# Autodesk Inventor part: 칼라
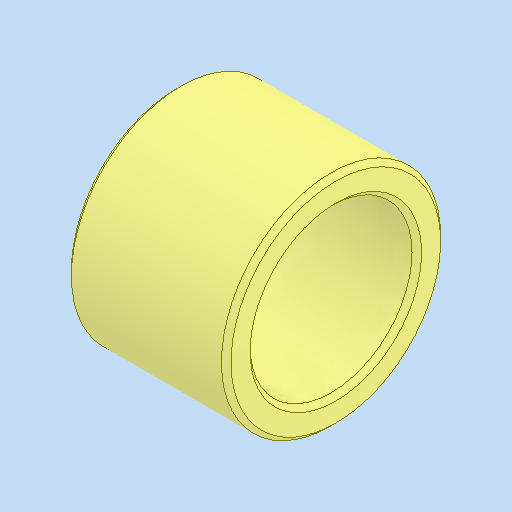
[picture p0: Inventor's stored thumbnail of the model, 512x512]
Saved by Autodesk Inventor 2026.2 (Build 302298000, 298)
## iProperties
Created: 2026-01
Part Number: 칼라
Material: 강철, 연강
Document SubType Name: Modeling
Designer: PC2-07
Density: 7.85 g/cm^3
Appearance: 기본값
Author: jhkim
Sending System: Autodesk Inventor 2026
Preprocessor: ST-DEVELOPER v20.1
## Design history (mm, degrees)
feature "솔리드1"
node "솔리드2"
